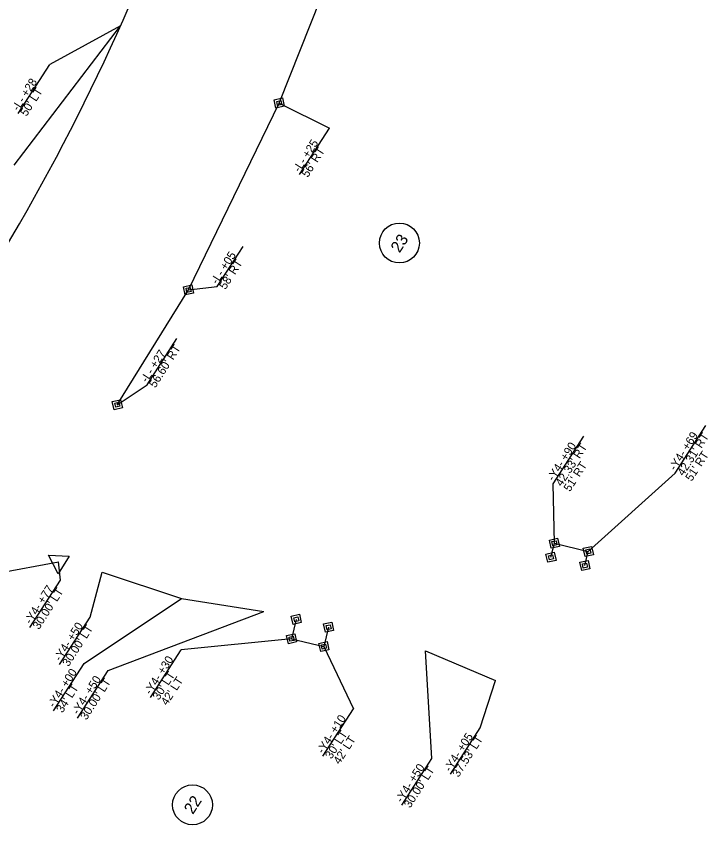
# Model space of a CAD drawing. Extents: x 1975689 to 1978251, y 778490 to 782347.
# Drawn here: x 1977155.6 to 1977571.4, y 780081.9 to 780567.9 of the extents above; entities that cross this region are included whole.
import ezdxf

# ---------------------------------------------------------------- set-up
doc = ezdxf.new("R2010")
doc.units = 0
for name, color, linetype in [('Prop Easement Construction', 7, 'Continuous'), ('Prop Easement Construction Station Offsets', 7, 'Continuous'), ('Prop Easement Permanent Drainage', 7, 'Continuous'), ('Prop Easement Permanent Drainage Station Offsets', 7, 'Continuous'), ('Prop Easement Permanent Utility', 7, 'Continuous'), ('Prop Easement Permanent Utility Station Offsets', 7, 'Continuous'), ('Prop Parcel Number CELL', 7, 'Continuous'), ('Prop ROW Marker CELL', 7, 'Continuous'), ('Prop ROW Permanent Easement CELL', 7, 'Continuous'), ('Prop ROW RW Lines', 7, 'Continuous'), ('Prop ROW Station Offsets', 7, 'Continuous')]:
    doc.layers.add(name, color=color, linetype=linetype)

msp = doc.modelspace()

# ---------------------------------------------------------------- linework, layer by layer
at = {"layer": 'Prop Easement Construction'}
for p, q in [((1977154.47, 780478.39), (1977218.35, 780562.05)), ((1977207.41, 780233.68), (1977255.06, 780218.01)), ((1977255.06, 780218.01), (1977304.59, 780210.11)), ((1977401.77, 780186.54), (1977443.73, 780168.61))]:
    msp.add_line(p, q, dxfattribs=at)
at = {"layer": 'Prop Easement Construction Station Offsets'}
for p, q in [((1977218.35, 780562.05), (1977175.83, 780538.88)), ((1977156.79, 780509.4), (1977175.83, 780538.88)), ((1977200.08, 780206.72), (1977207.41, 780233.68)), ((1977196.41, 780178.87), (1977255.06, 780218.01)), ((1977210.85, 780174.6), (1977304.59, 780210.11)), ((1977181.72, 780178.16), (1977200.08, 780206.72)), ((1977405.5, 780121.71), (1977401.77, 780186.54)), ((1977178.04, 780150.3), (1977196.41, 780178.87)), ((1977192.48, 780146.03), (1977210.85, 780174.6)), ((1977434.61, 780140.24), (1977443.73, 780168.61)), ((1977416.63, 780112.26), (1977434.61, 780140.24)), ((1977387.53, 780093.73), (1977405.5, 780121.71))]:
    msp.add_line(p, q, dxfattribs=at)
at = {"layer": 'Prop Easement Permanent Drainage'}
for p, q in [((1977477.13, 780242.69), (1977479.17, 780251.11)), ((1977479.17, 780251.11), (1977499.58, 780246.16)), ((1977497.53, 780237.71), (1977499.58, 780246.16)), ((1977324.03, 780205.39), (1977321.2, 780193.73)), ((1977343.46, 780200.68), (1977340.63, 780189.02)), ((1977321.2, 780193.73), (1977340.63, 780189.02))]:
    msp.add_line(p, q, dxfattribs=at)
at = {"layer": 'Prop Easement Permanent Drainage Station Offsets'}
for p, q in [((1977551.7, 780293.2), (1977570.17, 780321.82)), ((1977478.51, 780286.92), (1977496.89, 780315.41)), ((1977499.58, 780246.16), (1977551.7, 780293.2)), ((1977479.17, 780251.11), (1977478.51, 780286.92)), ((1977321.2, 780193.73), (1977254.74, 780186.97)), ((1977340.63, 780189.02), (1977358.43, 780151.56)), ((1977236.35, 780158.49), (1977254.74, 780186.97)), ((1977340.05, 780123.07), (1977358.43, 780151.56))]:
    msp.add_line(p, q, dxfattribs=at)
at = {"layer": 'Prop Easement Permanent Utility'}
for p, q in [((1977313.74, 780515.73), (1977352.24, 780612.29)), ((1977259.26, 780403.39), (1977313.74, 780515.73)), ((1977216.44, 780334.4), (1977259.26, 780403.39))]:
    msp.add_line(p, q, dxfattribs=at)
at = {"layer": 'Prop Easement Permanent Utility Station Offsets'}
for p, q in [((1977313.74, 780515.73), (1977343.97, 780500.72)), ((1977326, 780472.74), (1977343.97, 780500.72)), ((1977276.54, 780405.37), (1977292.07, 780429.55)), ((1977259.26, 780403.39), (1977276.54, 780405.37)), ((1977234.34, 780346.27), (1977252.31, 780374.25)), ((1977216.44, 780334.4), (1977234.34, 780346.27))]:
    msp.add_line(p, q, dxfattribs=at)
at = {"layer": 'Prop Parcel Number CELL'}
for p, q in [((1977386.02, 780431.59), (1977386.02, 780431.59)), ((1977261.64, 780093.88), (1977261.64, 780093.88))]:
    msp.add_line(p, q, dxfattribs=at)
for centre in [(1977386.02, 780431.59), (1977261.64, 780093.88)]:
    msp.add_circle(centre, 12, dxfattribs=at)
at = {"layer": 'Prop ROW Marker CELL'}
for p, q in [((1977313.74, 780515.73), (1977313.74, 780515.73)), ((1977259.26, 780403.39), (1977259.26, 780403.39)), ((1977216.44, 780334.4), (1977216.44, 780334.4)), ((1977479.17, 780251.11), (1977479.17, 780251.11)), ((1977499.58, 780246.16), (1977499.58, 780246.16)), ((1977477.13, 780242.69), (1977477.13, 780242.69)), ((1977181.17, 780240.04), (1977181.17, 780240.04)), ((1977497.53, 780237.71), (1977497.53, 780237.71)), ((1977324.03, 780205.4), (1977324.03, 780205.4)), ((1977343.46, 780200.68), (1977343.46, 780200.68)), ((1977321.2, 780193.73), (1977321.2, 780193.73)), ((1977340.63, 780189.02), (1977340.63, 780189.02))]:
    msp.add_line(p, q, dxfattribs=at)
msp.add_lwpolyline([(1977180.82, 780232.84), (1977175.11, 780243.94), (1977187.58, 780243.35)], close=True, dxfattribs=at)
at = {"layer": 'Prop ROW Permanent Easement CELL'}
for points in [[(1977310.72, 780517.68), (1977315.69, 780518.76), (1977316.77, 780513.79), (1977311.8, 780512.71)], [(1977312.23, 780516.71), (1977314.72, 780517.25), (1977315.26, 780514.76), (1977312.77, 780514.22)], [(1977256.23, 780405.33), (1977261.2, 780406.41), (1977262.28, 780401.44), (1977257.31, 780400.36)], [(1977257.74, 780404.36), (1977260.23, 780404.9), (1977260.77, 780402.41), (1977258.28, 780401.87)], [(1977213.41, 780336.35), (1977218.39, 780337.43), (1977219.47, 780332.45), (1977214.49, 780331.37)], [(1977214.92, 780335.37), (1977217.41, 780335.91), (1977217.95, 780333.43), (1977215.47, 780332.89)], [(1977476.15, 780253.06), (1977481.12, 780254.14), (1977482.2, 780249.17), (1977477.23, 780248.08)], [(1977477.66, 780252.09), (1977480.15, 780252.63), (1977480.69, 780250.14), (1977478.2, 780249.6)], [(1977496.55, 780248.11), (1977501.53, 780249.19), (1977502.61, 780244.22), (1977497.64, 780243.13)], [(1977498.07, 780247.14), (1977500.56, 780247.68), (1977501.1, 780245.19), (1977498.61, 780244.65)], [(1977474.1, 780244.63), (1977479.08, 780245.72), (1977480.16, 780240.74), (1977475.18, 780239.66)], [(1977475.62, 780243.66), (1977478.1, 780244.2), (1977478.64, 780241.71), (1977476.16, 780241.17)], [(1977494.51, 780239.66), (1977499.48, 780240.74), (1977500.56, 780235.77), (1977495.59, 780234.69)], [(1977496.02, 780238.69), (1977498.51, 780239.23), (1977499.05, 780236.74), (1977496.56, 780236.2)], [(1977321, 780207.34), (1977325.97, 780208.42), (1977327.05, 780203.45), (1977322.08, 780202.37)], [(1977322.51, 780206.37), (1977325, 780206.91), (1977325.54, 780204.42), (1977323.05, 780203.88)], [(1977340.43, 780202.63), (1977345.41, 780203.71), (1977346.49, 780198.73), (1977341.52, 780197.65)], [(1977341.95, 780201.65), (1977344.44, 780202.19), (1977344.98, 780199.71), (1977342.49, 780199.17)], [(1977318.17, 780195.68), (1977323.15, 780196.76), (1977324.23, 780191.79), (1977319.25, 780190.7)], [(1977319.68, 780194.71), (1977322.17, 780195.25), (1977322.71, 780192.76), (1977320.23, 780192.22)], [(1977337.61, 780190.97), (1977342.58, 780192.05), (1977343.66, 780187.07), (1977338.69, 780185.99)], [(1977339.12, 780189.99), (1977341.61, 780190.53), (1977342.15, 780188.05), (1977339.66, 780187.5)]]:
    msp.add_lwpolyline(points, close=True, dxfattribs=at)
at = {"layer": 'Prop ROW RW Lines'}
msp.add_line((1977114.05, 780227.31), (1977181.17, 780240.04), dxfattribs=at)
msp.add_arc((1975987.1, 781115.69), 1350, 315.73946, 340.62647, dxfattribs=at)
at = {"layer": 'Prop ROW Station Offsets'}
for p, q in [((1977182.29, 780228.97), (1977181.17, 780240.04)), ((1977163.92, 780200.41), (1977182.29, 780228.97))]:
    msp.add_line(p, q, dxfattribs=at)

# ---------------------------------------------------------------- texts
at = {"layer": 'Prop Easement Construction Station Offsets'}
for s, rotation, p in [('-L- +28', 57.1585, (1977156.9, 780510.57)), ("50' LT", 57.1585, (1977161.85, 780507.37)), ('-Y4- +50', 57.255, (1977182.17, 780179.84)), ("30.00' LT", 57.255, (1977187.12, 780176.65)), ('-Y4- +00', 57.255, (1977178.49, 780151.98)), ('-Y4- +50', 57.255, (1977192.93, 780147.72)), ("30.00' LT", 57.255, (1977197.89, 780144.53)), ("34' LT", 57.255, (1977183.45, 780148.8)), ('-Y4- +05', 57.2884, (1977416.59, 780113.32)), ("37.53' LT", 57.2884, (1977421.55, 780110.14)), ('-Y4- +50', 57.2884, (1977387.49, 780094.79)), ("30.00' LT", 57.2884, (1977392.45, 780091.61))]:
    msp.add_text(s, height=5, rotation=rotation, dxfattribs=at).set_placement(p)
at = {"layer": 'Prop Easement Permanent Drainage Station Offsets'}
for s, p in [('-Y4- +69', (1977551.8, 780294.37)), ("42.31' RT", (1977556.75, 780291.18)), ('-Y4- +90', (1977478.61, 780288.09)), ("42.33' RT", (1977483.56, 780284.89)), ("51' RT", (1977561.7, 780287.98)), ("51' RT", (1977488.51, 780281.7)), ('-Y4- +30', (1977236.45, 780159.66)), ("30' LT", (1977241.4, 780156.46)), ("42' LT", (1977246.36, 780153.27)), ('-Y4- +10', (1977340.15, 780124.24)), ("30' LT", (1977345.1, 780121.05)), ("42' LT", (1977350.05, 780117.85))]:
    msp.add_text(s, height=5, rotation=57.1585, dxfattribs=at).set_placement(p)
at = {"layer": 'Prop Easement Permanent Utility Station Offsets'}
for s, p in [('-L- +25', (1977325.96, 780473.8)), ("56' RT", (1977330.92, 780470.62)), ('-L- +05', (1977276.5, 780406.43)), ("58' RT", (1977281.46, 780403.25)), ('-L- +27', (1977234.3, 780347.34)), ("56.60' RT", (1977239.26, 780344.15))]:
    msp.add_text(s, height=5, rotation=57.2884, dxfattribs=at).set_placement(p)
at = {"layer": 'Prop Parcel Number CELL'}
for s, p in [('23', (1977386.13, 780425.25)), ('22', (1977261.87, 780087.74))]:
    msp.add_text(s, height=7, rotation=57.2884, dxfattribs=at).set_placement(p)
at = {"layer": 'Prop ROW Station Offsets'}
for s, p in [('-Y4- +77', (1977164.37, 780202.09)), ("30.00' LT", (1977169.33, 780198.9))]:
    msp.add_text(s, height=5, rotation=57.255, dxfattribs=at).set_placement(p)

doc.saveas('drawing.dxf')
